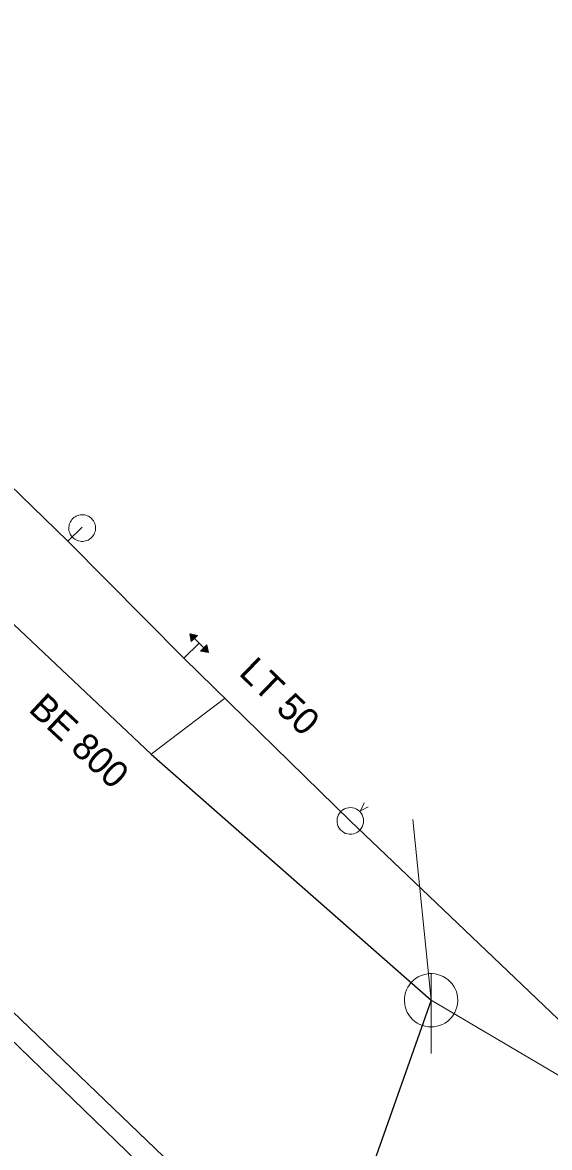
# Model space of a CAD drawing. Extents: x -807203 to -805207, y -993656 to -992505.
# Drawn here: x -805958.79 to -805939.05, y -993323.34 to -993281.18 of the extents above; entities that cross this region are included whole.
import ezdxf

# ---------------------------------------------------------------- set-up
doc = ezdxf.new("R2010")
doc.units = 0
doc.header["$LTSCALE"] = 0.4
for name, color, linetype, lineweight in [('1', 7, 'Continuous', 13), ('11', 7, 'Continuous', 13), ('13', 7, 'Continuous', 13), ('14', 7, 'Continuous', 25), ('17', 7, 'Continuous', 25), ('22', 7, 'Continuous', 13), ('23', 7, 'Continuous', 13), ('34', 7, 'Continuous', 13)]:
    doc.layers.add(name, color=color, linetype=linetype, lineweight=lineweight)

msp = doc.modelspace()

# ---------------------------------------------------------------- linework, layer by layer
at = {"layer": '11'}
for p, q in [((-805951.222, -993306.512), (-805953.97, -993308.596)), ((-805944.177, -993311.042), (-805943.489, -993317.82)), ((-805962.21, -993316.399), (-805947.879, -993330.26))]:
    msp.add_line(p, q, dxfattribs=at)
msp.add_lwpolyline([(-805919.353, -993327.844), (-805921.873, -993330.572), (-805943.489, -993317.82)], dxfattribs=at)
at = {"layer": '13'}
msp.add_line((-805957.092, -993300.616), (-805956.557, -993300.094), dxfattribs=at)
msp.add_lwpolyline([(-805946.515, -993311.099), (-805934.429, -993322.629), (-805912.935, -993296.079), (-805909.259, -993277.126), (-805870.365, -993236.01)], dxfattribs=at)
at = {"layer": '14'}
msp.add_line((-805943.489, -993317.82), (-805947.879, -993330.26), dxfattribs=at)
msp.add_lwpolyline([(-805980.85, -993282.69), (-805968.73, -993294.715), (-805966.495, -993296.778), (-805953.969, -993308.596), (-805943.489, -993317.82)], dxfattribs=at)
at = {"layer": '17'}
msp.add_line((-805952.748, -993305.003), (-805946.515, -993311.099), dxfattribs=at)
for points in [[(-805970.428, -993287.685), (-805964.557, -993293.37), (-805960.618, -993297.208), (-805957.092, -993300.616), (-805952.748, -993305.003)], [(-805980.27, -993297.811), (-805964.539, -993313.096), (-805944.059, -993332.754), (-805925.796, -993349.072), (-805905.688, -993366.883), (-805894.556, -993375.978), (-805881.298, -993386.71), (-805877.651, -993389.561), (-805871.269, -993394.798), (-805850.666, -993411.467), (-805839.3, -993421.037), (-805830.275, -993428.564)]]:
    msp.add_lwpolyline(points, dxfattribs=at)
at = {"layer": '22'}
msp.add_line((-805943.489, -993319.82), (-805943.488, -993316.82), dxfattribs=at)
msp.add_lwpolyline([(-805942.489, -993317.82), (-805942.494, -993317.711), (-805942.512, -993317.603), (-805942.542, -993317.497), (-805942.582, -993317.396), (-805942.634, -993317.299), (-805942.696, -993317.209), (-805942.768, -993317.126), (-805942.848, -993317.052), (-805942.936, -993316.986), (-805943.03, -993316.931), (-805943.13, -993316.886), (-805943.235, -993316.853), (-805943.342, -993316.831), (-805943.451, -993316.821), (-805943.561, -993316.823), (-805943.669, -993316.837), (-805943.776, -993316.862), (-805943.879, -993316.899), (-805943.977, -993316.948), (-805944.069, -993317.006), (-805944.155, -993317.075), (-805944.232, -993317.152), (-805944.301, -993317.238), (-805944.36, -993317.33), (-805944.408, -993317.428), (-805944.445, -993317.531), (-805944.471, -993317.638), (-805944.485, -993317.746), (-805944.488, -993317.856), (-805944.478, -993317.965), (-805944.457, -993318.072), (-805944.423, -993318.176), (-805944.379, -993318.276), (-805944.324, -993318.371), (-805944.258, -993318.459), (-805944.184, -993318.539), (-805944.101, -993318.611), (-805944.011, -993318.673), (-805943.915, -993318.725), (-805943.813, -993318.766), (-805943.708, -993318.796), (-805943.6, -993318.814), (-805943.49, -993318.82), (-805943.381, -993318.814), (-805943.273, -993318.796), (-805943.168, -993318.767), (-805943.066, -993318.726), (-805942.969, -993318.674), (-805942.879, -993318.612), (-805942.796, -993318.541), (-805942.721, -993318.461), (-805942.656, -993318.373), (-805942.6, -993318.279), (-805942.556, -993318.179), (-805942.522, -993318.075), (-805942.5, -993317.967), (-805942.49, -993317.858)], close=True, dxfattribs=at)
at = {"layer": '23'}
for points in [[(-805956.201, -993299.775), (-805956.24, -993299.739), (-805956.282, -993299.708), (-805956.327, -993299.683), (-805956.375, -993299.661), (-805956.424, -993299.644), (-805956.476, -993299.634), (-805956.527, -993299.628), (-805956.579, -993299.627), (-805956.631, -993299.632), (-805956.683, -993299.642), (-805956.733, -993299.658), (-805956.782, -993299.679), (-805956.827, -993299.705), (-805956.868, -993299.735), (-805956.908, -993299.769), (-805956.944, -993299.809), (-805956.974, -993299.85), (-805957.001, -993299.896), (-805957.023, -993299.942), (-805957.04, -993299.992), (-805957.05, -993300.045), (-805957.056, -993300.096), (-805957.057, -993300.149), (-805957.053, -993300.201), (-805957.042, -993300.251), (-805957.025, -993300.302), (-805957.005, -993300.349), (-805956.979, -993300.395), (-805956.947, -993300.437), (-805956.914, -993300.477), (-805956.875, -993300.512), (-805956.833, -993300.543), (-805956.787, -993300.57), (-805956.74, -993300.592), (-805956.691, -993300.607), (-805956.64, -993300.618), (-805956.588, -993300.625), (-805956.535, -993300.625), (-805956.483, -993300.62)], [(-805956.483, -993300.62), (-805956.432, -993300.61), (-805956.382, -993300.594), (-805956.334, -993300.574), (-805956.288, -993300.547), (-805956.247, -993300.516), (-805956.207, -993300.482), (-805956.172, -993300.444), (-805956.141, -993300.402), (-805956.114, -993300.356), (-805956.093, -993300.309), (-805956.076, -993300.259), (-805956.064, -993300.209), (-805956.059, -993300.156), (-805956.058, -993300.104), (-805956.063, -993300.052), (-805956.073, -993300), (-805956.089, -993299.95), (-805956.11, -993299.902), (-805956.137, -993299.857), (-805956.167, -993299.815), (-805956.201, -993299.775), (-805956.24, -993299.739), (-805956.282, -993299.708), (-805956.327, -993299.683), (-805956.375, -993299.661), (-805956.424, -993299.644), (-805956.476, -993299.634), (-805956.527, -993299.628), (-805956.579, -993299.627), (-805956.631, -993299.632), (-805956.683, -993299.642), (-805956.733, -993299.658), (-805956.782, -993299.679), (-805956.827, -993299.705), (-805956.868, -993299.735), (-805956.908, -993299.769), (-805956.944, -993299.809), (-805956.974, -993299.85), (-805957.001, -993299.896)], [(-805957.001, -993299.896), (-805957.023, -993299.942), (-805957.04, -993299.992), (-805957.05, -993300.045), (-805957.056, -993300.096), (-805957.057, -993300.149), (-805957.053, -993300.201), (-805957.042, -993300.251), (-805957.025, -993300.302), (-805957.005, -993300.349), (-805956.979, -993300.395), (-805956.947, -993300.437), (-805956.914, -993300.477), (-805956.875, -993300.512), (-805956.833, -993300.543), (-805956.787, -993300.57), (-805956.74, -993300.592), (-805956.691, -993300.607), (-805956.64, -993300.618), (-805956.588, -993300.625), (-805956.535, -993300.625), (-805956.483, -993300.62), (-805956.432, -993300.61), (-805956.382, -993300.594), (-805956.334, -993300.574), (-805956.288, -993300.547), (-805956.247, -993300.516), (-805956.207, -993300.482), (-805956.172, -993300.444), (-805956.141, -993300.402), (-805956.114, -993300.356), (-805956.093, -993300.309), (-805956.076, -993300.259), (-805956.064, -993300.209), (-805956.059, -993300.156), (-805956.058, -993300.104), (-805956.063, -993300.052), (-805956.073, -993300), (-805956.089, -993299.95), (-805956.11, -993299.902)], [(-805956.11, -993299.902), (-805956.137, -993299.857), (-805956.167, -993299.815), (-805956.201, -993299.775)], [(-805945.845, -993310.567), (-805946.136, -993310.718), (-805945.993, -993310.423)]]:
    msp.add_lwpolyline(points, dxfattribs=at)
msp.add_lwpolyline([(-805946.159, -993311.447), (-805946.109, -993311.388), (-805946.07, -993311.322), (-805946.04, -993311.25), (-805946.023, -993311.175), (-805946.017, -993311.098), (-805946.023, -993311.021), (-805946.041, -993310.946), (-805946.07, -993310.875), (-805946.111, -993310.809), (-805946.16, -993310.749), (-805946.219, -993310.699), (-805946.284, -993310.657), (-805946.355, -993310.627), (-805946.43, -993310.609), (-805946.507, -993310.602), (-805946.584, -993310.606), (-805946.66, -993310.622), (-805946.731, -993310.651), (-805946.798, -993310.689), (-805946.858, -993310.738), (-805946.909, -993310.796), (-805946.952, -993310.86), (-805946.983, -993310.931), (-805947.004, -993311.005), (-805947.012, -993311.082), (-805947.009, -993311.159), (-805946.994, -993311.235), (-805946.967, -993311.307), (-805946.929, -993311.375), (-805946.882, -993311.435), (-805946.825, -993311.488), (-805946.76, -993311.532), (-805946.691, -993311.565), (-805946.617, -993311.587), (-805946.54, -993311.596), (-805946.463, -993311.594), (-805946.387, -993311.58), (-805946.315, -993311.555), (-805946.246, -993311.518), (-805946.185, -993311.472)], close=True, dxfattribs=at)
at = {"layer": '34'}
for p, q in [((-805952.474, -993304.38), (-805952.528, -993304.087)), ((-805952.5, -993304.092), (-805952.523, -993304.114)), ((-805952.469, -993304.102), (-805952.514, -993304.146)), ((-805952.439, -993304.106), (-805952.512, -993304.177)), ((-805952.411, -993304.111), (-805952.507, -993304.204)), ((-805952.381, -993304.12), (-805952.5, -993304.235)), ((-805952.353, -993304.125), (-805952.495, -993304.262)), ((-805952.325, -993304.132), (-805952.489, -993304.291)), ((-805952.294, -993304.135), (-805952.486, -993304.322)), ((-805952.264, -993304.144), (-805952.479, -993304.352)), ((-805952.179, -993304.439), (-805952.747, -993305.002)), ((-805951.884, -993304.528), (-805952.095, -993304.74)), ((-805951.876, -993304.558), (-805952.064, -993304.748)), ((-805951.873, -993304.589), (-805952.033, -993304.751)), ((-805951.866, -993304.617), (-805952.005, -993304.757)), ((-805951.861, -993304.645), (-805951.978, -993304.763)), ((-805951.852, -993304.675), (-805951.947, -993304.77)), ((-805951.848, -993304.703), (-805951.919, -993304.775)), ((-805951.844, -993304.733), (-805951.888, -993304.778)), ((-805951.834, -993304.764), (-805951.857, -993304.787))]:
    msp.add_line(p, q, dxfattribs=at)
for points in [[(-805952.528, -993304.087), (-805952.236, -993304.15), (-805952.474, -993304.38)], [(-805952.122, -993304.735), (-805951.83, -993304.792), (-805952.528, -993304.087)], [(-805951.83, -993304.792), (-805951.89, -993304.499), (-805952.122, -993304.735)]]:
    msp.add_lwpolyline(points, dxfattribs=at)

# ---------------------------------------------------------------- texts
at = {"layer": '1'}
for s, rotation, p in [('LT 50 ', 316, (-805950.729, -993305.598)), ('BE 800', 317, (-805958.61, -993306.964))]:
    msp.add_text(s, height=1, rotation=rotation, dxfattribs=at).set_placement(p)

doc.saveas('drawing.dxf')
